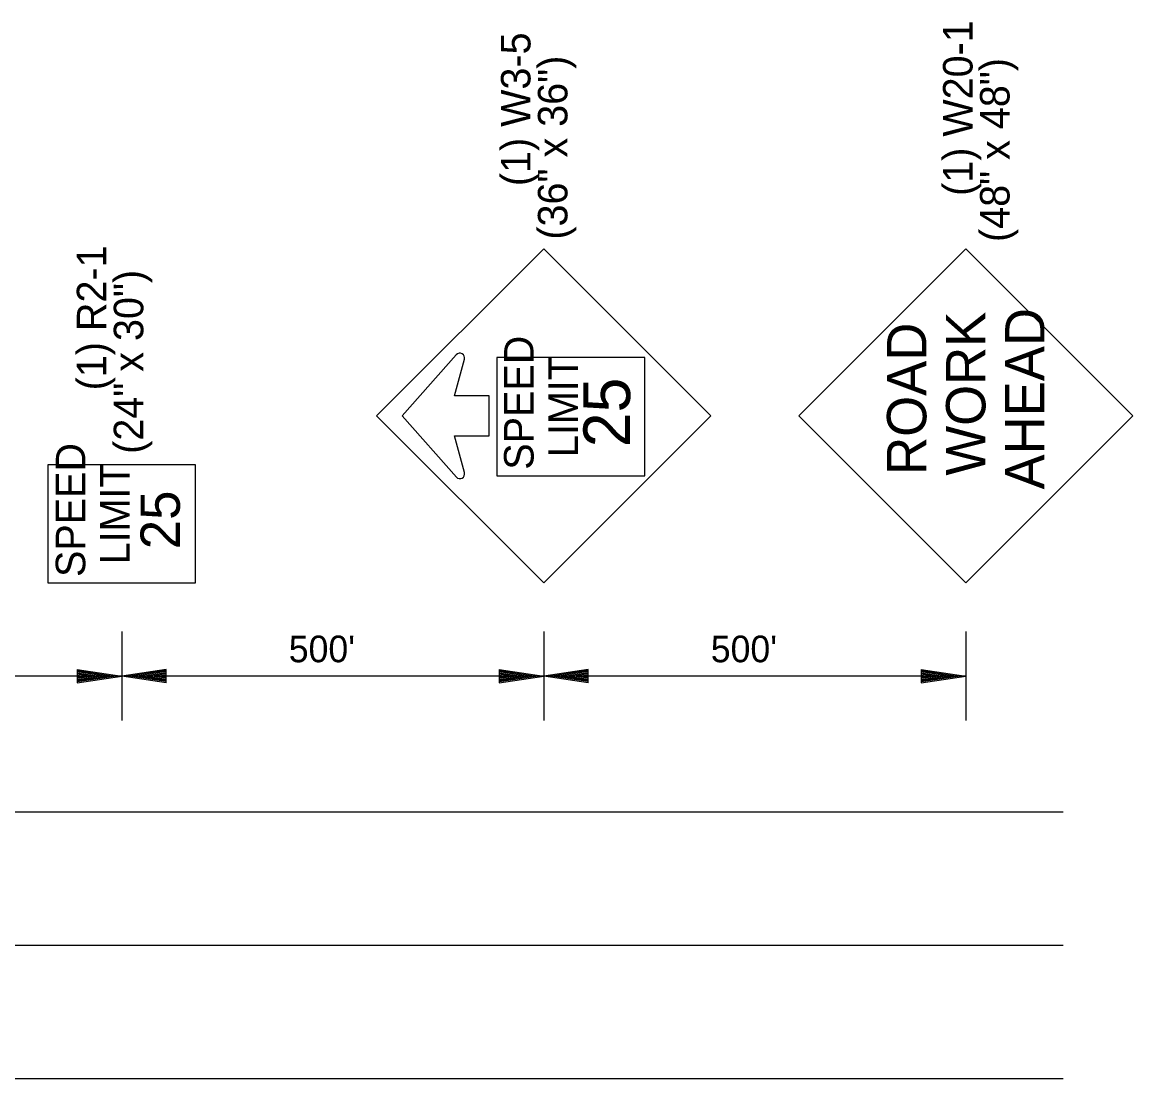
# Model space of a CAD drawing. Extents: x 1368648 to 1927880, y -1037443 to 380209.
# Drawn here: x 1371716.5 to 1371942.1, y 377862.4 to 378076.9 of the extents above; entities that cross this region are included whole.
import ezdxf

# ---------------------------------------------------------------- set-up
doc = ezdxf.new("R2010")
doc.units = 0
for name, color, linetype in [('Default', 7, 'Continuous'), ('R_Draft', 7, 'Continuous'), ('R_Signs', 7, 'Continuous'), ('R_Signs_Annot', 7, 'Continuous')]:
    doc.layers.add(name, color=color, linetype=linetype)

# ---------------------------------------------------------------- blocks, each defined once
blk = doc.blocks.new('ARROW')
at = {"layer": 'R_Draft'}
for p, q in [((-2, 0.3), (0, 0)), ((-2, 0.3), (-2, -0.3)), ((-2, 0.25), (-0.334, 0)), ((-2, 0.199), (-0.678, 0)), ((-2, 0.149), (-1.011, 0)), ((-2, 0.097), (-1.35, 0)), ((-2, 0.047), (-1.684, 0)), ((-2, -0.3), (0, 0)), ((-2, -0.098), (-1.35, 0)), ((-2, -0.199), (-0.678, 0)), ((-2, -0.25), (-0.334, 0)), ((-2, -0.149), (-1.011, 0)), ((-2, -0.047), (-1.684, 0))]:
    blk.add_line(p, q, dxfattribs=at)

msp = doc.modelspace()

# ---------------------------------------------------------------- linework, layer by layer
at = {"layer": 'Default'}
for p, q in [((1371736.7, 377953.17), (1371736.7, 377935.12)), ((1371736.7, 377953.17), (1371736.7, 377935.12)), ((1371822.43, 377953.17), (1371822.43, 377935.12)), ((1371822.43, 377953.17), (1371822.43, 377935.12)), ((1371908.17, 377953.17), (1371908.17, 377935.12)), ((1371736.7, 377944.15), (1371650.96, 377944.15)), ((1371736.7, 377944.15), (1371727.67, 377944.15)), ((1371736.7, 377944.15), (1371727.67, 377944.15)), ((1371822.43, 377944.15), (1371736.7, 377944.15)), ((1371822.43, 377944.15), (1371813.41, 377944.15)), ((1371822.43, 377944.15), (1371813.41, 377944.15)), ((1371908.17, 377944.15), (1371822.43, 377944.15)), ((1371908.17, 377944.15), (1371899.15, 377944.15)), ((1371928, 377916.51), (1371222.63, 377916.51)), ((1371928, 377889.43), (1371222.63, 377889.43)), ((1371928, 377862.36), (1371222.63, 377862.36))]:
    msp.add_line(p, q, dxfattribs=at)
at = {"layer": 'R_Signs'}
for p, q in [((1371822.43, 378030.93), (1371788.49, 377996.99)), ((1371856.37, 377996.99), (1371822.43, 378030.93)), ((1371804.67, 378009.38), (1371793.67, 377996.99)), ((1371804.28, 378001.08), (1371806.32, 378008.49)), ((1371811.35, 378001.08), (1371804.28, 378001.08)), ((1371811.35, 377992.96), (1371811.35, 378001.08)), ((1371788.49, 377996.99), (1371822.43, 377963.05)), ((1371793.67, 377996.99), (1371804.69, 377984.57)), ((1371822.43, 377963.05), (1371856.37, 377996.99)), ((1371806.34, 377985.46), (1371804.28, 377992.96)), ((1371804.28, 377992.96), (1371811.35, 377992.96))]:
    msp.add_line(p, q, dxfattribs=at)
for points in [[(1371874.23, 377996.99), (1371908.17, 377963.05), (1371942.11, 377996.99), (1371908.17, 378030.93)], [(1371842.96, 377984.83), (1371842.96, 378008.86), (1371812.93, 378008.86), (1371812.93, 377984.83)], [(1371751.7, 377963.05), (1371751.7, 377987.05), (1371721.7, 377987.05), (1371721.7, 377963.05)]]:
    msp.add_lwpolyline(points, close=True, dxfattribs=at)
for centre, start, end in [((1371805.39, 378008.75), 344.6222, 138.4138), ((1371805.41, 377985.21), 221.5862, 15.3778)]:
    msp.add_arc(centre, 0.961, start, end, dxfattribs=at)

# ---------------------------------------------------------------- block references
at = {"layer": 'Default', "xscale": 4.512500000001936, "yscale": 4.512499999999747}
for p in [(1371736.7, 377944.15), (1371822.43, 377944.15), (1371908.17, 377944.15)]:
    msp.add_blockref('ARROW', p, dxfattribs=at)
at = {"layer": 'Default', "xscale": 4.512500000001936, "yscale": 4.512499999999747, "rotation": 180}
for p in [(1371736.7, 377944.15), (1371822.43, 377944.15)]:
    msp.add_blockref('ARROW', p, dxfattribs=at)

# ---------------------------------------------------------------- texts
at = {"layer": 'Default'}
for p in [(1371770.63, 377946.95), (1371856.37, 377946.95)]:
    msp.add_text("500'", height=5.415, rotation=360, dxfattribs=at).set_placement(p)
at = {"layer": 'R_Signs'}
for s, height, p in [('WORK', 8, (1371912.17, 377984.87)), ('AHEAD', 8, (1371924.17, 377982.04)), ('ROAD', 8, (1371900.17, 377985.01)), ('SPEED', 6, (1371820.37, 377986.06)), ('LIMIT', 6, (1371829.37, 377988.62)), ('25', 9.5, (1371839.99, 377990.62)), ('SPEED', 6, (1371729.29, 377964.27)), ('LIMIT', 6, (1371738.29, 377966.83)), ('25', 8, (1371748.51, 377969.92))]:
    msp.add_text(s, height=height, rotation=90, dxfattribs=at).set_placement(p)
at = {"layer": 'R_Signs_Annot'}
for s, p in [('(1) W20-1', (1371909.56, 378041.67)), ('(1) W3-5', (1371819.74, 378043.66)), ('(36" x 36")', (1371827.25, 378032.79)), ('(48" x 48")', (1371917.07, 378032.31)), ('(1) R2-1', (1371733.57, 378002.18)), ('(24" x 30")', (1371741.08, 377989.28))]:
    msp.add_text(s, height=6, rotation=90, dxfattribs=at).set_placement(p)

doc.saveas('drawing.dxf')
